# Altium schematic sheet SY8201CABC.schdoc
size 127 x 101 mm
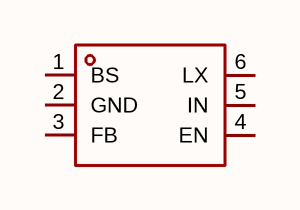
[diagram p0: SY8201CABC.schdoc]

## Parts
U?  sy8201cabc  [SOT-23-6_L2.9-W1.6-P0.95-LS2.8-BR]  (value not drawn)

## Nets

Not connected (* = marked no-connect by the designer): U? 1(BS) 2(GND) 3(FB) 4(EN) 5(IN) 6(LX)

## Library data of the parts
U? = sy8201cabc: 功能类型:降压型;工作电压:4.5V~27V;输出电压:1.2V;输出电流:1A;输出类型:固定;; Manufacturer: Silergy(矽力杰); AddInBom: yes; ModelId: 18da8f6c14a34920b3e136b5c401a119; ModelName: SOT-23-6_L2.9-W1.6-H1.5-LS2.8-P0.95; ModelTransform: 110.73671,114.173,0,180,0,0,0.001,-0.003,0; Function: 降压型; Output Voltage: 1.2V; Output Current: 1A; Frequency - Switching: 1.15MHz; Synchronous Rectifier: 是; Number of Outputs: 1; Topology: 降压式; Quiescent Current: 400uA; Switch tube (built-in/external): 内置; Output Type: 固定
